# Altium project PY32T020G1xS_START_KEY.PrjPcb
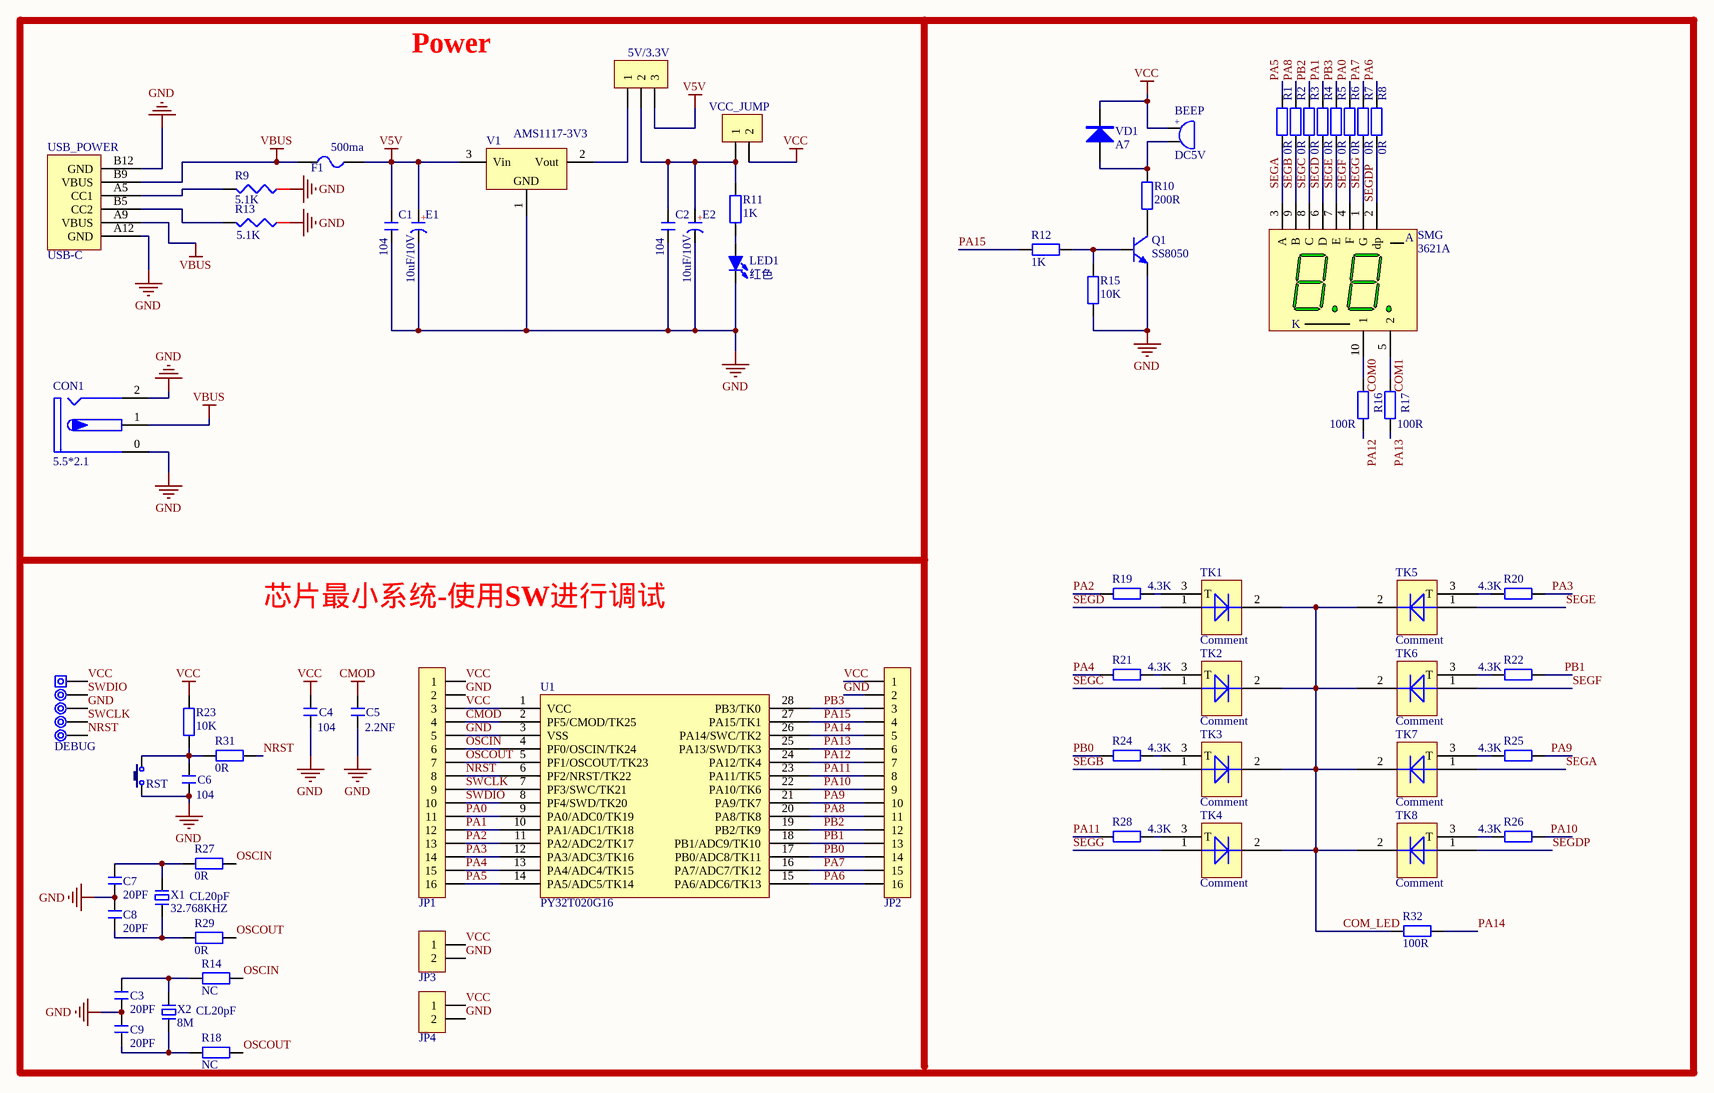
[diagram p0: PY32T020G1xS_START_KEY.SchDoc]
1 sheet, 70 parts. Net scope: global (net labels, ports and power ports of the same name join across sheets).
Board file: PY32T020G1xS_START_KEY.PcbDoc

## Sheet PY32T020G1xS_START_KEY.SchDoc
size A3

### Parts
5V/3.3V  HDR-1X3  [HDR2.54-LI-3P]  (value not drawn)
BEEP  DC5V  [BEEP 5x9x5.5]
C1  104  [C 0603_L]
C2  104  [C 0603_L]
C3  20PF  [C 0603_L]
C4  104  [C 0603_L]
C5  2.2NF  [C 0603_L]
C6  104  [C 0603_L]
C7  20PF  [C 0603_L]
C8  20PF  [C 0603_L]
C9  20PF  [C 0603_L]
CON1  5.5*2.1  [DC-005P]
DEBUG  ISP  [ISP_DIP_2.54_5P]  (value not drawn)
E1  10uF/10V  [C 0805_L]
E2  10uF/10V  [C 0805_L]
F1  500ma  [FU 0805]
JP1  HDR-1X16  [HDR2.54-LI-16P]  (value not drawn)
JP2  HDR-1X16  [HDR2.54-LI-16P]  (value not drawn)
JP3  HDR-1X2  [XH2.54-WI-2P]  (value not drawn)
JP4  HDR-1X2  [XH2.54-WI-2P]  (value not drawn)
LED1  红色  [LED 0805R]
Q1  SS8050  [SOT23-3L]
R1  0R  [R 0603_L]
R2  0R  [R 0603_L]
R3  0R  [R 0603_L]
R4  0R  [R 0603_L]
R5  0R  [R 0603_L]
R6  0R  [R 0603_L]
R7  0R  [R 0603_L]
R8  0R  [R 0603_L]
R9  5.1K  [R 0603_L]
R10  200R  [R 0603_L]
R11  1K  [R 0603_L]
R12  1K  [R 0603_L]
R13  5.1K  [R 0603_L]
R14  NC  [R 0603_L]
R15  10K  [R 0603_L]
R16  100R  [R 0603_L]
R17  100R  [R 0603_L]
R18  NC  [R 0603_L]
R19  4.3K  [R 0603_L]
R20  4.3K  [R 0603_L]
R21  4.3K  [R 0603_L]
R22  4.3K  [R 0603_L]
R23  10K  [R 0603_L]
R24  4.3K  [R 0603_L]
R25  4.3K  [R 0603_L]
R26  4.3K  [R 0603_L]
R27  0R  [R 0603_L]
R28  4.3K  [R 0603_L]
R29  0R  [R 0603_L]
R31  0R  [R 0603_L]
R32  100R  [R 0603_L]
RST  6x6x5  [TSW SMD-3*6*5]  (value not drawn)
SMG  3621A  [SMG 0.36-2P]
TK1  Comment  [TLEDL]
TK2  Comment  [TLEDR]
TK3  Comment  [TLEDL]
TK4  Comment  [TLEDR]
TK5  Comment  [TLEDR]
TK6  Comment  [TLEDR]
TK7  Comment  [TLEDR]
TK8  Comment  [TLEDL]
U1  PY32T020G16
USB_POWER  USB-C  [USB-C/S_C]
V1  AMS1117-3V3  [SOT223_N]
VCC_JUMP  HDR-1X2  [HDR2.54-LI-2P]  (value not drawn)
VD1  A7  [SOD-123]
X1  32.768KHZ  负载电容: CL20pF  [OSC-3x8-WI-A]
X2  8M  负载电容: CL20pF  [OSC HC-49S]

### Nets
CMOD: C5.2 JP1.4 U1.2(PF5/CMOD/TK25)
GND: C1.1 C2.1 C3.1 C4.1 C5.1 C6.1 C7.1 C8.2 C9.2 CON1.0 CON1.2 DEBUG.3 E1.2(K) E2.2(K) JP1.2 JP1.5 JP2.2 JP3.2 JP4.2 LED1.2(K) Q1.2(B) R9.1 R13.1 R15.1 RST.1 U1.3(VSS) USB_POWER.A12(GND) USB_POWER.B12(GND) V1.1(GND)
V5V: 5V/3.3V.3 C1.2 E1.1(A) F1.2 V1.3(Vin)
VBUS: CON1.1 F1.1 USB_POWER.A9(VBUS) USB_POWER.B9(VBUS)
VCC: BEEP.1 C4.2 DEBUG.1 JP1.1 JP1.3 JP2.1 JP3.1 JP4.1 R23.2 U1.1(VCC) VCC_JUMP.2 VD1.K
COM0: R16.1 SMG.10(1)
COM1: R17.1 SMG.5(2)
COM_LED: R32.1 TK1.2 TK2.2 TK3.2 TK4.2 TK5.2 TK6.2 TK7.2 TK8.2
NRST: DEBUG.5 JP1.8 R31.1 U1.6(PF2/NRST/TK22)
OSCIN: JP1.6 R14.1 R27.1 U1.4(PF0/OSCIN/TK24)
OSCOUT: JP1.7 R18.1 R29.1 U1.5(PF1/OSCOUT/TK23)
PA0: JP1.11 R6.1 U1.9(PA0/ADC0/TK19)
PA1: JP1.12 R4.1 U1.10(PA1/ADC1/TK18)
PA2: JP1.13 R19.1 U1.11(PA2/ADC2/TK17)
PA3: JP1.14 R20.1 U1.12(PA3/ADC3/TK16)
PA4: JP1.15 R21.1 U1.13(PA4/ADC4/TK15)
PA5: JP1.16 R1.1 U1.14(PA5/ADC5/TK14)
PA6: JP2.16 R8.1 U1.15(PA6/ADC6/TK13)
PA7: JP2.15 R7.1 U1.16(PA7/ADC7/TK12)
PA8: JP2.11 R2.1 U1.20(PA8/TK8)
PA9: JP2.10 R25.1 U1.21(PA9/TK7)
PA10: JP2.9 R26.1 U1.22(PA10/TK6)
PA11: JP2.8 R28.1 U1.23(PA11/TK5)
PA12: JP2.7 R16.2 U1.24(PA12/TK4)
PA13: JP2.6 R17.2 U1.25(PA13/SWD/TK3)
PA14: JP2.5 R32.2 U1.26(PA14/SWC/TK2)
PA15: JP2.4 R12.2 U1.27(PA15/TK1)
PB0: JP2.14 R24.1 U1.17(PB0/ADC8/TK11)
PB1: JP2.13 R22.1 U1.18(PB1/ADC9/TK10)
PB2: JP2.12 R3.1 U1.19(PB2/TK9)
PB3: JP2.3 R5.1 U1.28(PB3/TK0)
SEGA: R1.2 SMG.3(A) TK7.1
SEGB: R2.2 SMG.9(B) TK3.1
SEGC: R3.2 SMG.8(C) TK2.1
SEGD: R4.2 SMG.6(D) TK1.1
SEGDP: R8.2 SMG.2(dp) TK8.1
SEGE: R5.2 SMG.7(E) TK5.1
SEGF: R6.2 SMG.4(F) TK6.1
SEGG: R7.2 SMG.1(G) TK4.1
SWCLK: DEBUG.4 JP1.9 U1.7(PF3/SWC/TK21)
SWDIO: DEBUG.2 JP1.10 U1.8(PF4/SWD/TK20)
Net5V/3.3V_1: 5V/3.3V.1 V1.2(Vout)
Net5V/3.3V_2: 5V/3.3V.2 C2.2 E2.1(A) R11.2 VCC_JUMP.1
NetBEEP_2: BEEP.2 R10.2 VD1.A
NetC3_2: C3.2 R14.2 X2.1
NetC6_2: C6.2 R23.1 R31.2 RST.2
NetC7_2: C7.2 R27.2 X1.1
NetC8_1: C8.1 R29.2 X1.2
NetC9_1: C9.1 R18.2 X2.2
NetLED1_1: LED1.1(A) R11.1
NetQ1_1: Q1.1(E) R12.1 R15.2
NetQ1_3: Q1.3(C) R10.1
NetR9_2: R9.2 USB_POWER.A5(CC1)
NetR13_2: R13.2 USB_POWER.B5(CC2)
NetR19_2: R19.2 TK1.3(T)
NetR20_2: R20.2 TK5.3(T)
NetR21_2: R21.2 TK2.3(T)
NetR22_2: R22.2 TK6.3(T)
NetR24_2: R24.2 TK3.3(T)
NetR25_2: R25.2 TK7.3(T)
NetR26_2: R26.2 TK8.3(T)
NetR28_2: R28.2 TK4.3(T)

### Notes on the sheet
- Power
- 芯片最小系统-使用SW进行调试

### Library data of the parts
5V/3.3V = Header 3: 3P接插件; 版权归属: 源创客
BEEP = BEEP: 蜂鸣器; 版权归属: 源创客
C1-C9 = C: 无极性贴片电容; 版权归属: 源创客; 材质: X7R
CON1 = DC-005P: 带屏蔽DC电源接口; 版权归属: 源创客
DEBUG = ISP_5Pin: 程序下载端口; 版权归属: 源创客
E1 E2 = C-CM: 贴片电解电容; 版权归属: 源创客
F1 = FU: 贴片保险丝; 版权归属: 源创客
JP1 JP2 = Header 16: 16P接插件; 版权归属: 源创客
JP3 JP4 VCC_JUMP = Header 2: 2P接插件; 版权归属: 源创客
LED1 = LED-SMD: 贴片LED; 版权归属: 源创客
Q1 = 8050-DIP: 高频放大-NPN型; 版权归属: 源创客; 属性: 40V 1.5A 1W 100MHZ
R1-R8 R10-R12 R14-R29 R31 R32 = R: 贴片电阻; 版权归属: 源创客
R9 R13 = R
RST = TSW DIP-2Pin-6x6: 2脚直插6x6轻触开关; BOM名称: 2脚轻触开关; 版权归属: 源创客
SMG = 3621A: 0.36寸2位共阴数码管; 版权归属: 源创客
TK1-TK8 = TLED
USB_POWER = USB-C_6P/S: USB-C_6P型母接口; BOM名称: USB-C型母接口; 版权归属: 源创客
V1 = AMS1117: 三端稳压芯片; BOM名称: 稳压芯片; 版权归属: 源创客
VD1 = DIODE
X1 X2 = XTAL-2P: 2脚无源脚晶振; 版权归属: 源创客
